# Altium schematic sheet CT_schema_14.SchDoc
size 389 x 385 mm
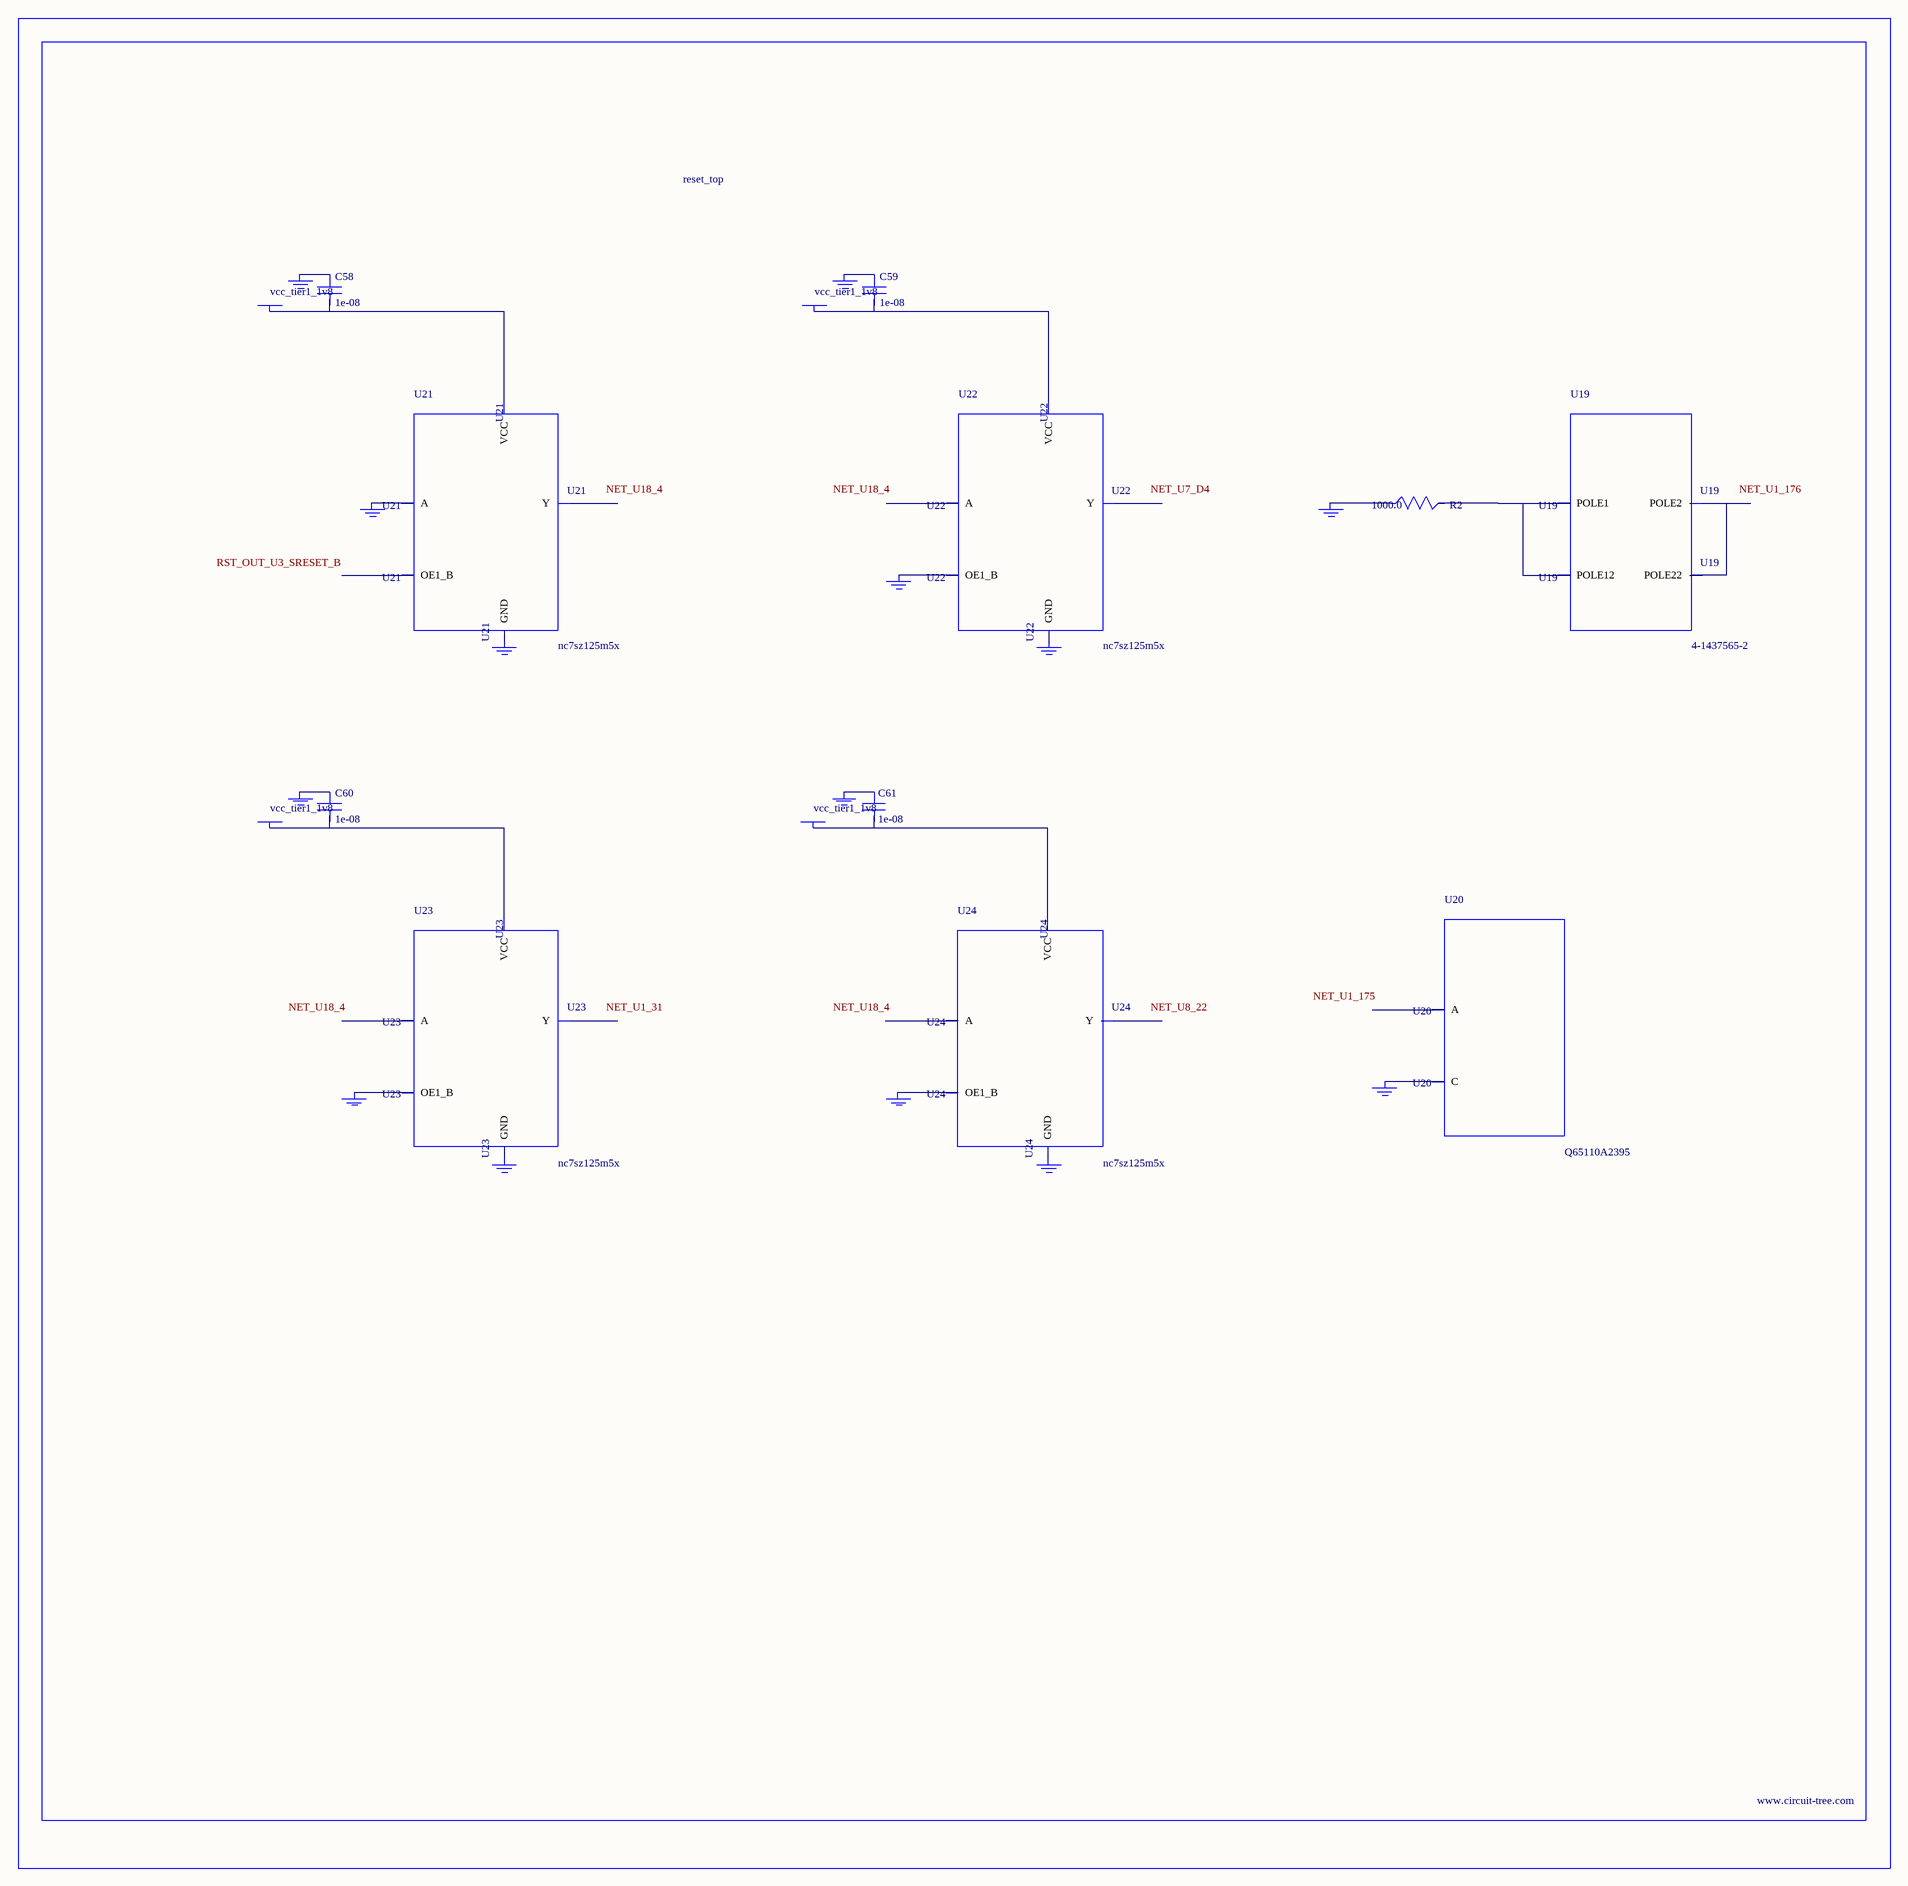
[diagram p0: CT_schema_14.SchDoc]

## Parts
BORDER13  (no value)
C58  1e-08  [C0402]
C59  1e-08  [C0402]
C60  1e-08  [C0402]
C61  1e-08  [C0402]
GND_INSTANCE_13_0  (no value)
GND_INSTANCE_13_1  (no value)
GND_INSTANCE_13_2  (no value)
GND_INSTANCE_13_3  (no value)
GND_INSTANCE_13_4  (no value)
GND_INSTANCE_13_5  (no value)
GND_INSTANCE_13_6  (no value)
GND_INSTANCE_13_7  (no value)
GND_INSTANCE_13_8  (no value)
GND_INSTANCE_13_9  (no value)
GND_INSTANCE_13_10  (no value)
GND_INSTANCE_13_11  (no value)
GND_INSTANCE_13_12  (no value)
GND_INSTANCE_13_13  (no value)
POWER_INSTANCE_13_0  vcc_tier1_1v8
POWER_INSTANCE_13_1  vcc_tier1_1v8
POWER_INSTANCE_13_2  vcc_tier1_1v8
POWER_INSTANCE_13_3  vcc_tier1_1v8
R2  1000.0  [R0603]
U19  4-1437565-2  [SW_4-1437565-2]
U20  Q65110A2395  [LGM67K-G1J2-24-Z]
U21  nc7sz125m5x  [NC7SZ125M5X]
U22  nc7sz125m5x  [NC7SZ125M5X]
U23  nc7sz125m5x  [NC7SZ125M5X]
U24  nc7sz125m5x  [NC7SZ125M5X]

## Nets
NetC58_1: C58.1 GND_INSTANCE_13_2.0(GND)
NetC58_2: C58.2 POWER_INSTANCE_13_0.0(PWR) U21.5(VCC)
NetC59_1: C59.1 GND_INSTANCE_13_5.0(GND)
NetC59_2: C59.2 POWER_INSTANCE_13_1.0(PWR) U22.5(VCC)
NetC60_1: C60.1 GND_INSTANCE_13_8.0(GND)
NetC60_2: C60.2 POWER_INSTANCE_13_2.0(PWR) U23.5(VCC)
NetC61_1: C61.1 GND_INSTANCE_13_11.0(GND)
NetC61_2: C61.2 POWER_INSTANCE_13_3.0(PWR) U24.5(VCC)
NetGND_INSTANCE_13_0_0: GND_INSTANCE_13_0.0(GND) R2.1
NetGND_INSTANCE_13_1_0: GND_INSTANCE_13_1.0(GND) U20.C
NetGND_INSTANCE_13_3_0: GND_INSTANCE_13_3.0(GND) U21.2(A)
NetGND_INSTANCE_13_4_0: GND_INSTANCE_13_4.0(GND) U21.3(GND)
NetGND_INSTANCE_13_6_0: GND_INSTANCE_13_6.0(GND) U22.1(OE1_B)
NetGND_INSTANCE_13_7_0: GND_INSTANCE_13_7.0(GND) U22.3(GND)
NetGND_INSTANCE_13_9_0: GND_INSTANCE_13_9.0(GND) U23.1(OE1_B)
NetGND_INSTANCE_13_10_0: GND_INSTANCE_13_10.0(GND) U23.3(GND)
NetGND_INSTANCE_13_12_0: GND_INSTANCE_13_12.0(GND) U24.1(OE1_B)
NetGND_INSTANCE_13_13_0: GND_INSTANCE_13_13.0(GND) U24.3(GND)
NetR2_2: R2.2 U19.1(POLE1) U19.2(POLE12)
NetU19_3: U19.3(POLE2) U19.4(POLE22)

Not connected (* = marked no-connect by the designer): U20 A; U21 1(OE1_B) 4(Y); U22 2(A) 4(Y); U23 2(A) 4(Y); U24 2(A) 4(Y)

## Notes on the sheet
- Labels drawn without touching a wire or pin: NET_U1_31, NET_U1_175, NET_U1_176, NET_U7_D4, NET_U8_22, NET_U18_4, RST_OUT_U3_SRESET_B

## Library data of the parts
BORDER13 = BORDER_PAGE13
C58-C61 = C0402C103K3RAC
GND_INSTANCE_13_0-GND_INSTANCE_13_13 = GND
POWER_INSTANCE_13_0-POWER_INSTANCE_13_3 = PWR
R2 = RC0603JR-071KL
